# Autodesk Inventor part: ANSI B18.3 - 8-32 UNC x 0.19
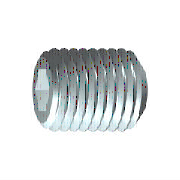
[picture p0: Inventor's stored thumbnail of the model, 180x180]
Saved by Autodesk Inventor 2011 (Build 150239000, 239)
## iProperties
IsCustomPart: 0
Created: 2008-02
Part Number: ANSI B18.3 - 8-32 UNC x 0.19
Material: Steel, Mild
Description: Hexagon Socket Set Screw - Flat Point
Document SubType Name: Modeling
Standard: ANSI B18.3
Standard Revision: 2003
Standards Organization: ANSI
Language: en-US
Size Designation: 8-32 UNC x 0.19
Categories: <MemberInstance><Categories><Category DisplayName="Fasteners" InternalName="e4da775c-781d-43d5-af7c-5136215cf5a6" Mnemonic="FSTN"><Category DisplayName="Bolts"
Density: 7.86 g/cm^3
Mass: 0.426476 g
Surface Area: 0.989445 cm^2
Volume: 0.054259 cm^3
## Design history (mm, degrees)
revolve "Body" stored, may be unused: angle "d6" = 90 deg
sketch "Sketch2"
  geometry: L1 (-0.572, 0.991)-(0.572, 0.991); L2 (0.572, 0.991)-(1.144, 0); L3 (1.144, 0)-(0.572, -0.991); L4 (0.572, -0.991)-(-0.572, -0.991); L5 (-0.572, -0.991)-(-1.144, 0); L6 (-1.144, 0)-(-0.572, 0.991); A1 r 1.144 centre (0, 0) between (-0.572, 0.991) and (0.572, 0.991) reference; 2 further points
  constraints: 12 end point, 2 point on circle, 1 coincident, 1 horizontal, 11 other
extrude "Slot" join sketch "Sketch2" taper "d9" = 0 deg; stored distance "d21" = 10
workaxis "Work Axis1"
workplane "Work Plane1"
body "Solid1"
chamfer "Chamfer1" distance "d7" = 0.48691 (= -0.5 x GD1 + 0.5 x NND); stored, may be unused: angle "d8" = 45 deg (= FAWI), second distance "d29" = 0.48691 (= -0.5 x GD1 + 0.5 x NND)
feature "Thread" dims "d11" = 4.826 (= NLG), "d12" = 0
chamfer "Chamfer2" distance "d13" = 0.48691 (= -0.5 x GD1 + 0.5 x NND); stored, may be unused: angle "d14" = 45 deg (= FAWI), second distance "d30" = 0.48691 (= -0.5 x GD1 + 0.5 x NND)
sketch "Sketch1"
  geometry: L1 (0, 0)-(1.88, 0); L2 (4.826, 1.144)-(4.826, 2.083); L3 (4.826, 2.083)-(0, 2.083); L4 (4.826, 1.144)-(2.54, 1.144); L5 (2.54, 1.144)-(1.88, 0); L6 (0, -0.417)-(0, 2.499) reference; L7 (0, 2.083)-(0, 0)
  constraints: 13 end point, 3 parallel, 1 collinear, 1 perpendicular, 1 point on line
  dimensions: "d0" = 2.286 distance of L2.start L4.end (= INTI); "d1" = 60 deg angle of L5 L1; "d2" = 4.1656 diameter of L3 L1 (= NND); "d3" = 2.28769 diameter of L4 L1 (= 1.1547 x SW); "d5" = 4.826 distance from line of L2 L3.end (= NLG)
other parameters: "NND" = 4.1656 [user parameter; used in 5 equation terms], "NLG" = 4.826 [user parameter; used in 2 equation terms], "INTI" = 2.286 [user parameter; used in 1 equation term], "FAWI" = 45 deg [user parameter; used in 3 equation terms], "SW" = 1.9812 [user parameter; used in 2 equation terms], "GD1" = 3.19177 [user parameter; used in 4 equation terms], "d4" = 0, "FAWI1" = 45 deg (= FAWI) [user parameter], "d15" = 0, "d31" = 0, "SPD" = 2.2098 [user parameter], "SEWI" = 90 deg [user parameter], "TOA" = 30 deg [user parameter], "ZLG" = 1.0922 [user parameter], "ZD" = 2.7686 [user parameter], "HHPTC" = 0.79375 [user parameter], "PTC" = 0.79375 (computed from TPU) [user parameter], "THREADDIA" = 4.1656 [user parameter], "OPR" = 3.1242 [user parameter], "E0" = 2.28829 (= 1.155 x SW) [user parameter]
